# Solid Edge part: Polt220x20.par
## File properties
Author: Türk
Template: Iso Part.par
Last saved by: Türk
Revision: 14
Application: Solid Edge
Accuracy: 0,990
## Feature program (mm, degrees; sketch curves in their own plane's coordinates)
thread "unnamed Thread 1"
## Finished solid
Body 1: solid body, 23 faces, 45 edges, 24 vertices.
  Faces by surface: plane 21, cylinder 2
  Edges by curve: line 42, circle 3
Bounding box of the edges (mm): 24.000 x 239.500 x 27.713, from (-12, -10, -13.8564) to (12, 229.5, 13.8564).
Cylindrical faces by radius (mm): R10 x2
Planar faces by outward normal: +x 1, +y 2, -x 1, -y 1, oblique 16
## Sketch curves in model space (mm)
circle centre (0, 0, 0) radius 13.8564
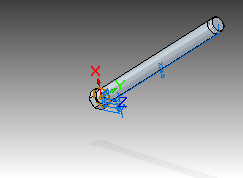
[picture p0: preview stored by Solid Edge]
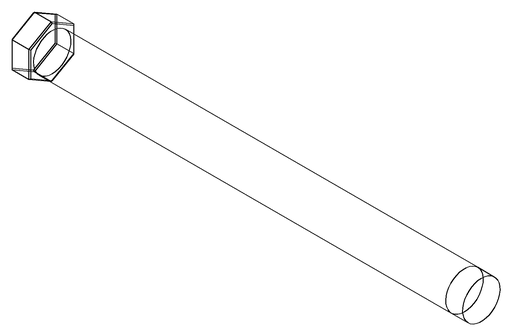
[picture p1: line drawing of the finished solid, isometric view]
